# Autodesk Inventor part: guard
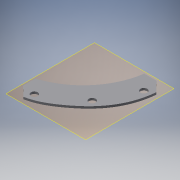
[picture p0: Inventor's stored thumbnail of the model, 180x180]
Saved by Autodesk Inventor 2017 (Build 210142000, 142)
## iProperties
Created: 2017-05
Part Number: guard
Material: ABS Plastic
Document SubType Name: Modeling
Designer: 1717440
Density: 1.06 g/cm^3
Appearance: Smooth - White
Author: 1717440
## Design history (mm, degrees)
workplane "Work Plane1"
sketch "Sketch1"
  geometry: L1 (18.414, 41.452)-(9.499, 41.452) reference; L2 (-38.276, -14.325)-(-38.276, -23.327) reference; L3 (-38.276, -23.327)-(-38.276, -26.185) reference; L4 (-38.276, -26.185)-(-28.844, -35.157) reference; L5 (30.642, 31.846)-(21.272, 41.452) reference; L6 (21.272, 41.452)-(18.414, 41.452) reference; C1 r 3.225 at (23.412, 27.176) reference; C2 r 3.225 at (-25.835, -27.792) reference; C3 r 3.225 at (7.037, -5.574) reference; A1 r 68.588 centre (-58.386, 51.249) between (-38.276, -14.325) and (9.499, 41.452) reference; 1 further point
extrude "Extrusion1" new body sketch "Sketch1" distance "d0" = 2; taper "d1" = 0 deg
body "Solid1"
node "Reference1"
